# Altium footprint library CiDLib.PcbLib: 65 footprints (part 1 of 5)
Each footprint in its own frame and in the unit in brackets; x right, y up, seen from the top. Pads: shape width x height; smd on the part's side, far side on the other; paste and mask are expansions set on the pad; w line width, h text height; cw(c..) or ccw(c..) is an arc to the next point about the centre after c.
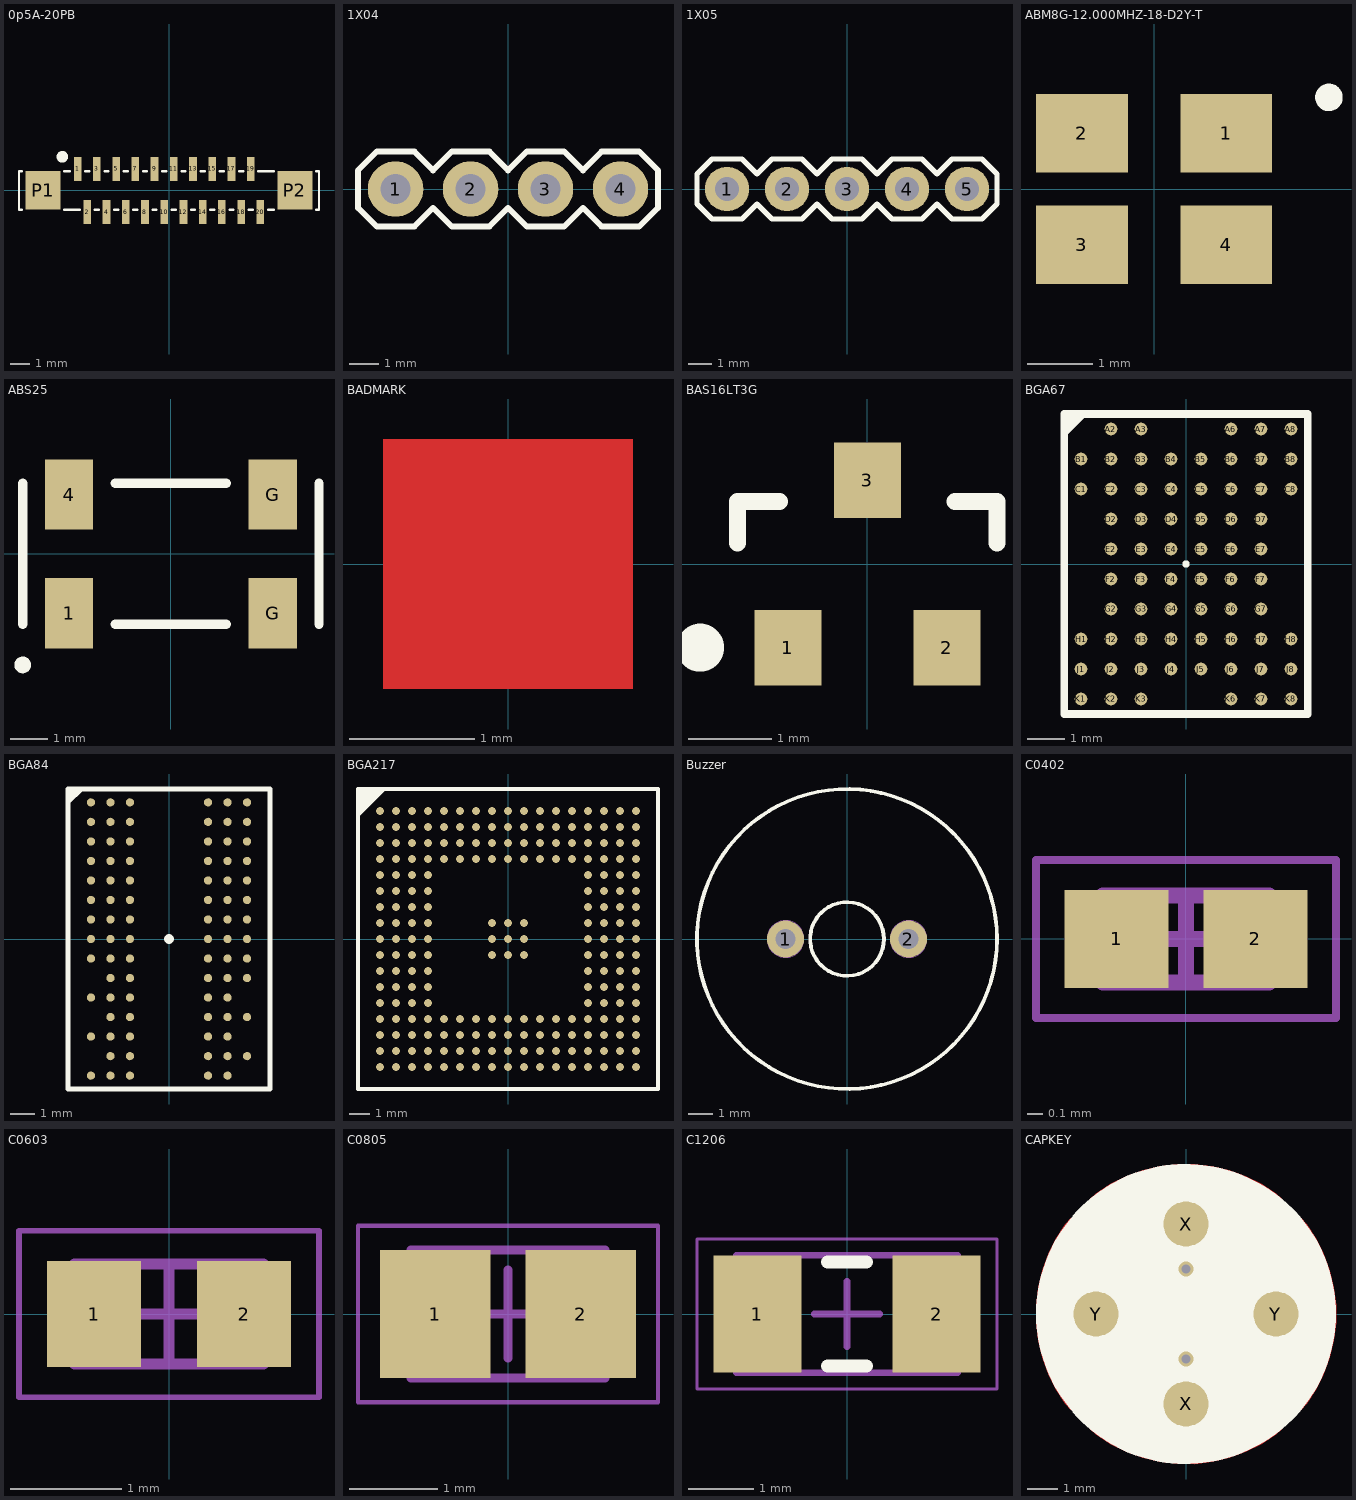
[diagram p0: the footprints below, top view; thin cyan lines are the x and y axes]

## 0p5A-20PB [mm]
pads (22):
  rect 0.4x1.25 smd: 1(-4.75,1.125) 2(-4.25,-1.125) 3(-3.75,1.125) 4(-3.25,-1.125) 5(-2.75,1.125) 6(-2.25,-1.125) 7(-1.75,1.125) 8(-1.25,-1.125) 9(-0.75,1.125) 10(-0.25,-1.125) 11(0.25,1.125) 12(0.75,-1.125) 13(1.25,1.125) 14(1.75,-1.125) 15(2.25,1.125) 16(2.75,-1.125) 17(3.25,1.125) 18(3.75,-1.125) 19(4.25,1.125) 20(4.75,-1.125)
  rect 1.8x2 smd: P1(-6.55,0) P2(6.55,0)
Top Overlay:
  circle w0.3: c-5.55,1.75 r0.15
  lines w0.127: -7.65,-1 -7.8,-1 -7.8,1 -7.65,1 ; -5.45,-1 -4.65,-1 ; -5.45,1 -5.15,1 ; -4.35,1 -4.15,1 ; -3.85,-1 -3.65,-1 ; -3.35,1 -3.15,1 ; -2.85,-1 -2.65,-1 ; -2.35,1 -2.15,1 ; -1.85,-1 -1.65,-1 ; -1.35,1 -1.15,1 ; -0.85,-1 -0.65,-1 ; -0.35,1 -0.15,1 ; 0.15,-1 0.35,-1 ; 0.65,1 0.85,1 ; 1.15,-1 1.35,-1 ; 1.65,1 1.85,1 ; 2.15,-1 2.35,-1 ; 2.65,1 2.85,1 ; 3.15,-1 3.35,-1 ; 3.65,1 3.85,1 ; 4.15,-1 4.35,-1 ; 4.65,1 5.45,1 ; 5.15,-1 5.45,-1 ; 7.65,-1 7.8,-1 7.8,1 7.65,1
Top Paste:
  rectangle: 6.65,-0.8 7.25,-0.1
  rectangle: 5.85,-0.8 6.45,-0.1
  rectangle: 6.65,0.1 7.25,0.8
  rectangle: 5.85,0.1 6.45,0.8
  rectangle: -6.45,-0.8 -5.85,-0.1
  rectangle: -7.25,-0.8 -6.65,-0.1
  rectangle: -6.45,0.1 -5.85,0.8
  rectangle: -7.25,0.1 -6.65,0.8
Top Solder:
  rectangle: -7.55,-1.1 -5.55,1.1
  rectangle: 5.55,-1.1 7.55,1.1
3D body: height 5, standoff 0, extent -7.5,-1 7.5,1

## 1X04 [mil]
pads (4):
  round 74 hole 40: 1(-150,0) 2(-50,0) 3(50,0) 4(150,0)
Top Overlay:
  lines w8: -200,-25 -200,25 -175,50 -125,50 -100,25 -75,50 -25,50 0,25 25,50 75,50 100,25 125,50 175,50 200,25 200,-25 175,-50 125,-50 100,-25 75,-50 25,-50 0,-25 -25,-50 -75,-50 -100,-25 -125,-50 -175,-50 -200,-25

## 1X05 [mil]
pads (5):
  round 74 hole 40: 1(-200,0) 2(-100,0) 3(0,0) 4(100,0) 5(200,0)
Top Overlay:
  lines w8: -250,-25 -225,-50 -175,-50 -150,-25 -125,-50 -75,-50 -50,-25 -25,-50 25,-50 50,-25 75,-50 125,-50 150,-25 175,-50 225,-50 250,-25 250,25 225,50 175,50 150,25 125,50 75,50 50,25 25,50 -25,50 -50,25 -75,50 -125,50 -150,25 -175,50 -225,50 -250,25 -250,-25

## ABM8G-12.000MHZ-18-D2Y-T [mm]
pads (4):
  rect 1.4x1.2 smd: 1(1.1,0.85) 2(-1.1,0.85) 3(-1.1,-0.85) 4(1.1,-0.85)
Top Overlay:
  circle w0.203: c2.667,1.397 r0.108
3D body: height 1, standoff 0, extent -1.6,-1.25 1.6,1.25

## ABS25 [mm] "Crystal 32.768kHz"
pads (4):
  rect 1.3x1.9 smd: 1(-2.75,-1.6) 4(-2.75,1.6) G(2.75,-1.6) G(2.75,1.6)
Top Overlay:
  circle w0.25: c-4,-3 r0.1
  lines w0.254: -4,-1.9 -4,1.9 ; -1.5,-1.9 1.5,-1.9 ; -1.5,1.9 1.5,1.9 ; 4,-1.9 4,1.9

## BADMARK [mm]
Top Layer:
  rectangle: -1,-1 1,1
Top Solder:
  rectangle: -1.2,-1.2 1.2,1.2

## BAS16LT3G [mm]
pads (3):
  rect 0.8x0.9 smd mask+0.051: 1(-0.95,-1) 2(0.95,-1) 3(0,1)
Top Overlay:
  circle w0.5: c-2,-1 r0.036
  lines w0.203: -1.55,0.25 -1.55,0.75 -1.05,0.75 ; 1.05,0.75 1.55,0.75 1.55,0.25
3D body: height 1.21, standoff 0.1, extent -1.45,-0.65 1.45,0.65

## BGA67 [mm]
pads (67):
  rrect100% 0.34x0.34 smd: A2(-2,3.6) A3(-1.2,3.6) A6(1.2,3.6) A7(2,3.6) A8(2.8,3.6) B1(-2.8,2.8) B2(-2,2.8) B3(-1.2,2.8) B4(-0.4,2.8) B5(0.4,2.8) B6(1.2,2.8) B7(2,2.8) B8(2.8,2.8) C1(-2.8,2) C2(-2,2) C3(-1.2,2) C4(-0.4,2) C5(0.4,2) C6(1.2,2) C7(2,2) C8(2.8,2) D2(-2,1.2) D3(-1.2,1.2) D4(-0.4,1.2) D5(0.4,1.2) D6(1.2,1.2) D7(2,1.2) E2(-2,0.4) E3(-1.2,0.4) E4(-0.4,0.4) E5(0.4,0.4) E6(1.2,0.4) E7(2,0.4) F2(-2,-0.4) F3(-1.2,-0.4) F4(-0.4,-0.4) F5(0.4,-0.4) F6(1.2,-0.4) F7(2,-0.4) G2(-2,-1.2) G3(-1.2,-1.2) G4(-0.4,-1.2) G5(0.4,-1.2) G6(1.2,-1.2) G7(2,-1.2) H1(-2.8,-2) H2(-2,-2) H3(-1.2,-2) H4(-0.4,-2) H5(0.4,-2) H6(1.2,-2) H7(2,-2) H8(2.8,-2) J1(-2.8,-2.8) J2(-2,-2.8) J3(-1.2,-2.8) J4(-0.4,-2.8) J5(0.4,-2.8) J6(1.2,-2.8) J7(2,-2.8) J8(2.8,-2.8) K1(-2.8,-3.6) K2(-2,-3.6) K3(-1.2,-3.6) K6(1.2,-3.6) K7(2,-3.6) K8(2.8,-3.6)
Top Overlay:
  circle w0.1: c0,0 r0.05
  lines w0.127: -3.2,3.5 -2.7,4 ; -3.2,3.6 -2.8,4 ; -3.2,3.7 -2.9,4 ; -3.2,3.8 -3,4
  lines w0.203: -3.25,-4 -3.25,4 3.25,4 3.25,-4 -3.25,-4
Top Paste:
  drawing of 469 lines, arcs and shapes, not listed
3D body: height 1, standoff 0.26, extent -3.352,-4.102 3.352,4.102

## BGA84 [mil]
pads (84):
  rrect100% 13.39x13.39 smd: A1(-125.98,220.47) A2(-94.49,220.47) A3(-62.99,220.47) A7(62.99,220.47) A8(94.49,220.47) A9(125.98,220.47) B1(-125.98,188.98) B2(-94.49,188.98) B3(-62.99,188.98) B7(62.99,188.98) B8(94.49,188.98) B9(125.98,188.98) C1(-125.98,157.48) C2(-94.49,157.48) C3(-62.99,157.48) C7(62.99,157.48) C8(94.49,157.48) C9(125.98,157.48) D1(-125.98,125.98) D2(-94.49,125.98) D3(-62.99,125.98) D7(62.99,125.98) D8(94.49,125.98) D9(125.98,125.98) E1(-125.98,94.49) E2(-94.49,94.49) E3(-62.99,94.49) E7(62.99,94.49) E8(94.49,94.49) E9(125.98,94.49) F1(-125.98,62.99) F2(-94.49,62.99) F3(-62.99,62.99) F7(62.99,62.99) F8(94.49,62.99) F9(125.98,62.99) G1(-125.98,31.5) G2(-94.49,31.5) G3(-62.99,31.5) G7(62.99,31.5) G8(94.49,31.5) G9(125.98,31.5) H1(-125.98,0) H2(-94.49,0) H3(-62.99,0) H7(62.99,0) H8(94.49,0) H9(125.98,0) J1(-125.98,-31.5) J2(-94.49,-31.5) J3(-62.99,-31.5) J7(62.99,-31.5) J8(94.49,-31.5) J9(125.98,-31.5) K2(-94.49,-62.99) K3(-62.99,-62.99) K7(62.99,-62.99) K8(94.49,-62.99) K9(125.98,-62.99) L1(-125.98,-94.49) L2(-94.49,-94.49) L3(-62.99,-94.49) L7(62.99,-94.49) L8(94.49,-94.49) M2(-94.49,-125.98) M3(-62.99,-125.98) M7(62.99,-125.98) M8(94.49,-125.98) M9(125.98,-125.98) N1(-125.98,-157.48) N2(-94.49,-157.48) N3(-62.99,-157.48) N7(62.99,-157.48) N8(94.49,-157.48) P2(-94.49,-188.98) P3(-62.99,-188.98) P7(62.99,-188.98) P8(94.49,-188.98) P9(125.98,-188.98) R1(-125.98,-220.47) R2(-94.49,-220.47) R3(-62.99,-220.47) R7(62.99,-220.47) R8(94.49,-220.47)
Top Overlay:
  circle w7.87: c0,0 r3.94
  lines w5: -161.42,220.47 -141.73,240.16 ; -161.42,224.41 -145.67,240.16 ; -161.42,228.35 -149.61,240.16 ; -161.42,232.28 -153.54,240.16
  lines w8: -163.32,-242.06 163.32,-242.06 163.32,242.06 -163.32,242.06 -163.32,-242.06
Top Paste:
  drawing of 588 lines, arcs and shapes, not listed
3D body: height 39.37, standoff 10.24, extent -167.32,-246.06 167.32,246.06

## BGA217 [mm]
pads (217):
  rrect100% 0.4x0.4 smd: A1(-6.4,6.4) A2(-5.6,6.4) A3(-4.8,6.4) A4(-4,6.4) A5(-3.2,6.4) A6(-2.4,6.4) A7(-1.6,6.4) A8(-0.8,6.4) A9(0,6.4) A10(0.8,6.4) A11(1.6,6.4) A12(2.4,6.4) A13(3.2,6.4) A14(4,6.4) A15(4.8,6.4) A16(5.6,6.4) A17(6.4,6.4) B1(-6.4,5.6) B2(-5.6,5.6) B3(-4.8,5.6) B4(-4,5.6) B5(-3.2,5.6) B6(-2.4,5.6) B7(-1.6,5.6) B8(-0.8,5.6) B9(0,5.6) B10(0.8,5.6) B11(1.6,5.6) B12(2.4,5.6) B13(3.2,5.6) B14(4,5.6) B15(4.8,5.6) B16(5.6,5.6) B17(6.4,5.6) C1(-6.4,4.8) C2(-5.6,4.8) C3(-4.8,4.8) C4(-4,4.8) C5(-3.2,4.8) C6(-2.4,4.8) C7(-1.6,4.8) C8(-0.8,4.8) C9(0,4.8) C10(0.8,4.8) C11(1.6,4.8) C12(2.4,4.8) C13(3.2,4.8) C14(4,4.8) C15(4.8,4.8) C16(5.6,4.8) C17(6.4,4.8) D1(-6.4,4) D2(-5.6,4) D3(-4.8,4) D4(-4,4) D5(-3.2,4) D6(-2.4,4) D7(-1.6,4) D8(-0.8,4) D9(0,4) D10(0.8,4) D11(1.6,4) D12(2.4,4) D13(3.2,4) D14(4,4) D15(4.8,4) D16(5.6,4) D17(6.4,4) E1(-6.4,3.2) E2(-5.6,3.2) E3(-4.8,3.2) E4(-4,3.2) E14(4,3.2) E15(4.8,3.2) E16(5.6,3.2) E17(6.4,3.2) F1(-6.4,2.4) F2(-5.6,2.4) F3(-4.8,2.4) F4(-4,2.4) F14(4,2.4) F15(4.8,2.4) F16(5.6,2.4) F17(6.4,2.4) G1(-6.4,1.6) G2(-5.6,1.6) G3(-4.8,1.6) G4(-4,1.6) G14(4,1.6) G15(4.8,1.6) G16(5.6,1.6) G17(6.4,1.6) H1(-6.4,0.8) H2(-5.6,0.8) H3(-4.8,0.8) H4(-4,0.8) H8(-0.8,0.8) H9(0,0.8) H10(0.8,0.8) H14(4,0.8) H15(4.8,0.8) H16(5.6,0.8) H17(6.4,0.8) J1(-6.4,0) J2(-5.6,0) J3(-4.8,0) J4(-4,0) J8(-0.8,0) J9(0,0) J10(0.8,0) J14(4,0) J15(4.8,0) J16(5.6,0) J17(6.4,0) K1(-6.4,-0.8) K2(-5.6,-0.8) K3(-4.8,-0.8) K4(-4,-0.8) K8(-0.8,-0.8) K9(0,-0.8) K10(0.8,-0.8) K14(4,-0.8) K15(4.8,-0.8) K16(5.6,-0.8) K17(6.4,-0.8) L1(-6.4,-1.6) L2(-5.6,-1.6) L3(-4.8,-1.6) L4(-4,-1.6) L14(4,-1.6) L15(4.8,-1.6) L16(5.6,-1.6) L17(6.4,-1.6) M1(-6.4,-2.4) M2(-5.6,-2.4) M3(-4.8,-2.4) M4(-4,-2.4) M14(4,-2.4) M15(4.8,-2.4) M16(5.6,-2.4) M17(6.4,-2.4) N1(-6.4,-3.2) N2(-5.6,-3.2) N3(-4.8,-3.2) N4(-4,-3.2) N14(4,-3.2) N15(4.8,-3.2) N16(5.6,-3.2) N17(6.4,-3.2) P1(-6.4,-4) P2(-5.6,-4) P3(-4.8,-4) P4(-4,-4) P5(-3.2,-4) P6(-2.4,-4) P7(-1.6,-4) P8(-0.8,-4) P9(0,-4) P10(0.8,-4) P11(1.6,-4) P12(2.4,-4) P13(3.2,-4) P14(4,-4) P15(4.8,-4) P16(5.6,-4) P17(6.4,-4) R1(-6.4,-4.8) R2(-5.6,-4.8) R3(-4.8,-4.8) R4(-4,-4.8) R5(-3.2,-4.8) R6(-2.4,-4.8) R7(-1.6,-4.8) R8(-0.8,-4.8) R9(0,-4.8) R10(0.8,-4.8) R11(1.6,-4.8) R12(2.4,-4.8) R13(3.2,-4.8) R14(4,-4.8) R15(4.8,-4.8) R16(5.6,-4.8) R17(6.4,-4.8) T1(-6.4,-5.6) T2(-5.6,-5.6) T3(-4.8,-5.6) T4(-4,-5.6) T5(-3.2,-5.6) T6(-2.4,-5.6) T7(-1.6,-5.6) T8(-0.8,-5.6) T9(0,-5.6) T10(0.8,-5.6) T11(1.6,-5.6) T12(2.4,-5.6) T13(3.2,-5.6) T14(4,-5.6) T15(4.8,-5.6) T16(5.6,-5.6) T17(6.4,-5.6) U1(-6.4,-6.4) U2(-5.6,-6.4) U3(-4.8,-6.4) U4(-4,-6.4) U5(-3.2,-6.4) U6(-2.4,-6.4) U7(-1.6,-6.4) U8(-0.8,-6.4) U9(0,-6.4) U10(0.8,-6.4) U11(1.6,-6.4) U12(2.4,-6.4) U13(3.2,-6.4) U14(4,-6.4) U15(4.8,-6.4) U16(5.6,-6.4) U17(6.4,-6.4)
Top Overlay:
  lines w0.2: -7.4,7.3 -7.3,7.4 -7.1,7.4 -7.4,7.1 -7.4,6.9 -6.9,7.4 -6.7,7.4 -7.4,6.7 -7.4,6.5 -6.4,7.5 ; -7.5,6.2 -6.2,7.5 ; -7.5,6.2 -7.5,-7.5 7.5,-7.5 7.5,7.5 -6.2,7.5 ; -7.5,6.2 -7.5,7.5 -6.4,7.5 ; -6.4,7.5 -6.2,7.5
Top Paste:
  drawing of 1302 lines, arcs and shapes, not listed
Top Solder:
  drawing of 217 lines, arcs and shapes, not listed
3D body: height 1, standoff 0.26, extent -7.6,-7.6 7.6,7.6

## Buzzer [mil]
pads (2):
  round 59.06 hole 31.5: 1(-98.43,0) 2(98.43,0)
Top Overlay:
  circle w6: c0,0 r240.16
  circle w6: c0,0 r59.06
Mechanical 86:
  circle w0: c-98.43,0 r29.53
  circle w0: c98.43,0 r29.53
3D body: height 196.85, standoff 0, extent -240.14,-240.14 240.14,240.14

## C0402 [mm] "Chip Capacitor, 2-Leads, Body 1,00x0,50mm, IPC Medium Density"
height 0.55
pads (2):
  rect 0.66x0.62 smd mask+0.051: 1(-0.44,0) 2(0.44,0)
Mechanical 13:
  lines w0.1: -0.525,-0.275 0.525,-0.275 0.525,0.275 -0.525,0.275 -0.525,-0.275
Mechanical 15:
  lines w0.05: -0.95,-0.5 0.95,-0.5 0.95,0.5 -0.95,0.5 -0.95,-0.5
  lines w0.1: -0.275,0 0.275,0 ; 0,-0.275 0,0.275
3D body: height 0.55, standoff 0, extent 0.275,-0.275 0.525,0.275
3D body: height 0.55, standoff 0, extent -0.525,-0.275 -0.275,0.275
3D body: height 0.55, standoff 0, extent -0.275,-0.275 0.275,0.275

## C0603 [mm] "Chip Capacitor, 2-Leads, Body 1,60x0,80mm, IPC Medium Density"
height 0.9
pads (2):
  rect 0.85x0.95 smd: 1(-0.675,0) 2(0.675,0)
Mechanical 13:
  lines w0.1: -0.85,-0.45 -0.85,0.45 0.85,0.45 0.85,-0.45 -0.85,-0.45
Mechanical 15:
  lines w0.05: -1.35,-0.75 -1.35,0.75 1.35,0.75 1.35,-0.75 -1.35,-0.75
  lines w0.1: -0.45,0 0.45,0 ; 0,-0.45 0,0.45
3D body: height 0.9, standoff 0, extent -0.55,-0.45 0.55,0.45
3D body: height 0.9, standoff 0, extent -0.85,-0.45 -0.55,0.45
3D body: height 0.9, standoff 0, extent 0.55,-0.45 0.85,0.45

## C0805 [mm] "Chip Capacitor, 2-Leads, Body 2,00x1,25mm, IPC Medium Density"
height 1.25
pads (2):
  rect 1.25x1.45 smd: 1(-0.825,0) 2(0.825,0)
Mechanical 13:
  lines w0.1: -1.1,-0.725 -1.1,0.725 1.1,0.725 1.1,-0.725 -1.1,-0.725
Mechanical 15:
  lines w0.05: -1.7,-1 -1.7,1 1.7,1 1.7,-1 -1.7,-1
  lines w0.1: -0.5,0 0.5,0 ; 0,-0.5 0,0.5
3D body: height 1.25, standoff 0, extent -0.65,-0.725 0.65,0.725
3D body: height 1.25, standoff 0, extent -1.1,-0.725 -0.65,0.725
3D body: height 1.25, standoff 0, extent 0.65,-0.725 1.1,0.725

## C1206 [mm] "Chip Capacitor, 2-Leads, Body 3,20x1,60mm, IPC Medium Density"
height 1.2
pads (2):
  rect 1.35x1.8 smd: 1(-1.375,0) 2(1.375,0)
Top Overlay:
  lines w0.2: -0.3,-0.8 0.3,-0.8 ; -0.3,0.8 0.3,0.8
Mechanical 13:
  lines w0.1: -1.7,-0.9 -1.7,0.9 1.7,0.9 1.7,-0.9 -1.7,-0.9
Mechanical 15:
  lines w0.05: -2.3,-1.15 -2.3,1.15 2.3,1.15 2.3,-1.15 -2.3,-1.15
  lines w0.1: -0.5,0 0.5,0 ; 0,-0.5 0,0.5
3D body: height 1.2, standoff 0, extent -1.2,-0.9 1.2,0.9
3D body: height 1.2, standoff 0, extent -1.7,-0.9 -1.2,0.9
3D body: height 1.2, standoff 0, extent 1.2,-0.9 1.7,0.9

## CAPKEY [mm]
pads (4):
  round 1.5 smd paste-5 mask-2540: X(0,-3) X(0,3) Y(-3,0) Y(3,0)
via 0,-1.5 diameter 0.5 hole 0.3
via 0,1.5 diameter 0.5 hole 0.3
Top Layer:
  region: -3.83,-3.214 -4.017,-2.991 -4.337,-2.504 -4.599,-1.984 -4.798,-1.436 -4.932,-0.87 -5,-0.291 -5,0.291 -4.932,0.87 -4.798,1.436 -4.599,1.984 -4.337,2.504 -4.017,2.991 -3.83,3.214 -0.5,0
  region: -3.214,-3.83 0,-0.5 3.214,-3.83 2.991,-4.017 2.504,-4.337 1.984,-4.599 1.436,-4.798 0.87,-4.932 0.291,-5 -0.291,-5 -0.87,-4.932 -1.436,-4.798 -1.984,-4.599 -2.504,-4.337 -2.991,-4.017
  region: 0,0.5 -3.214,3.83 -2.991,4.017 -2.504,4.337 -1.984,4.599 -1.436,4.798 -0.87,4.932 -0.291,5 0.291,5 0.87,4.932 1.436,4.798 1.984,4.599 2.504,4.337 2.991,4.017 3.214,3.83
  region: 0.5,0 3.83,3.214 4.017,2.991 4.337,2.504 4.599,1.984 4.798,1.436 4.932,0.87 5,0.291 5,-0.291 4.932,-0.87 4.798,-1.436 4.599,-1.984 4.337,-2.504 4.017,-2.991 3.83,-3.214
  lines w0.203: -3,0 3,0
Bottom Layer:
  lines w0.203: 0,-1.5 0,1.5
Top Overlay:
  circle w6: c0,0 r2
